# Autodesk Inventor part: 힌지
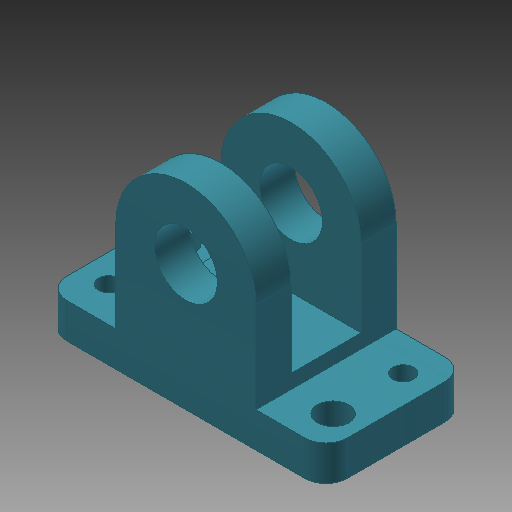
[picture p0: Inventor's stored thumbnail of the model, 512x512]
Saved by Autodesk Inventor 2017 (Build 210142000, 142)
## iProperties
Created: 2019-09
Part Number: 힌지
Material: 알루미늄 6061
Document SubType Name: Modeling
Designer: mduedu
Density: 2.71 g/cm^3
Appearance: 커뎃 파란색
Mass: 20.7756 g
Surface Area: 43.3328 cm^2
Volume: 7.66627 cm^3
Author: mduedu
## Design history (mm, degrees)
sketch "스케치1"
  geometry: L1 (-20, 0)-(20, 0); L2 (20, 0)-(20, 5); L3 (-20, 5)-(-20, 0); L4 (10, 5)-(10, 18); L5 (-10, 18)-(-10, 5); L6 (20, 5)-(10, 5); L7 (-10, 5)-(-20, 5); C1 r 4.5 at (0, 18); A1 r 10 centre (0, 18) between (10, 18) and (-10, 18); 2 further points
  constraints: 14 end point, 4 parallel, 2 centre point, 2 coincident, 2 point on circle, 2 tangent, 1 collinear, 1 horizontal, 1 midpoint, 1 perpendicular, 1 vertical, 1 vertical alignment
  dimensions: "d0" = 40 distance of L1.start L1.end; "d2" = 20 distance between parallel lines of L4 L5; "d3" = 18 distance from line of L1 A1.centre; "d4" = 5 distance of L1.end L2.end; "d5" = 9 diameter of C1
extrude "돌출1" new body sketch "스케치1" stored distance "d6" = 20; taper "d7" = 0 deg
sketch "스케치2"
  geometry: L1 (7, 5)-(37, 5); L2 (37, 5)-(37, -5); L3 (37, -5)-(7, -5); L4 (7, -5)-(7, 5); L5 (0, 10)-(0, -10) reference; 2 further points
  constraints: 8 end point, 2 parallel, 1 horizontal, 1 horizontal alignment, 1 midpoint, 1 perpendicular
  dimensions: "d8" = 7 distance between parallel lines of L5 L4; "d9" = 10 distance of L1.end L2.end; "d10" = 30 distance of L2.end L3.end
extrude "돌출2" cut sketch "스케치2" stored distance "d11" = 20; taper "d12" = 0 deg
sketch "스케치3"
  geometry: 3 further points
  dimensions: "d13" = 16 horizontal distance of point (6, 15) point (-10, 10); "d14" = 32 horizontal distance of point (-26, 5) point (6, 15); "d15" = 5 vertical distance of point (6, 15) point (-10, 10); "d16" = 10 vertical distance of point (-26, 5) point (6, 15)
hole "구멍1" sketch "스케치3" at (6, 15), (-26, 5) diameter "d17" = 3; stored, may be unused: countersink angle "d21" = 90 deg, drill point angle "d23" = 118 deg; dims "d18" = 6, "d19" = 4, "d20" = 2, "d22" = 8
sketch "스케치4"
  geometry: C1 r 1.5 at (6, 15) reference; C2 r 1.5 at (-26, 5) reference; 3 further points
  constraints: 2 horizontal alignment, 2 vertical alignment
hole "구멍2" sketch "스케치4" at (-26, 15), (6, 5) diameter "d24" = 4.5; stored, may be unused: countersink angle "d28" = 90 deg, drill point angle "d30" = 118 deg; dims "d25" = 6, "d26" = 4, "d27" = 2, "d29" = 8
fillet "모깎기1" dims "d31" = 3
node "솔리드1"
